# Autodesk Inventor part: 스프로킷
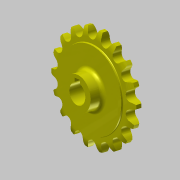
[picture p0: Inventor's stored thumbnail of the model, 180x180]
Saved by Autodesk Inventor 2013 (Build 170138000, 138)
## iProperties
Created: 2016-03
Part Number: 스프로킷
Material: 강철, 탄소
Document SubType Name: 판금
Designer: mduedu
Density: 7.87 g/cm^3
Mass: 301.818 g
Surface Area: 124.882 cm^2
Volume: 38.3505 cm^3
Sheet Metal Rule: 기본값
Author: mduedu
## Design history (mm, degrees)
sketch "스케치1"
  geometry: L1 (0, 5)-(29.5, 5); L2 (29.5, 5)-(29.5, 4.1); L3 (30, 3.6)-(33.625, 3.6); L4 (40, 2)-(40, 0); L5 (40, 0)-(0, 0); L6 (0, 0)-(0, 5); L7 (0, -5)-(29.5, -5); L8 (29.5, -5)-(29.5, -4.1); L9 (30, -3.6)-(33.625, -3.6); L10 (40, -2)-(40, 0); L11 (0, 0)-(0, -5); A1 r 13.5 centre (33.625, -9.9) between (40, 2) and (33.625, 3.6); A2 r 13.5 centre (33.625, 9.9) between (33.625, -3.6) and (40, -2); A3 r 0.5 centre (30, 4.1) between (29.5, 4.1) and (30, 3.6); A4 r 0.5 centre (30, -4.1) between (30, -3.6) and (29.5, -4.1); 2 further points
  constraints: 22 end point, 8 point on circle, 6 symmetric about line, 5 tangent, 4 centre point, 4 parallel, 4 point on line, 1 equal radius, 1 horizontal, 1 perpendicular, 1 other
  dimensions: "d0" = 80 diameter of L4 L6; "d2" = 59 diameter of L2 L6; "d3" = 1.6 vertical distance of L4.start L3.end; "d4" = 3.6 distance from line of L4.end L3; "d5" = 5 distance between parallel lines of L5 L1; "d6" = 13.5 radius of A1; "d15" = 0.5 radius of A3
revolve "회전1" sketch "스케치1" stored, may be unused: angle "d7" = 90 deg
sketch "스케치2" dims "d8" = 65.2, "d11" = 80
  geometry: L1 (0, 0)-(0, 32.6); A1 r 36.57 centre (0, 0) between (-16.231, 32.771) and (0, 36.57); A2 r 3.97 centre (0, 36.57) between (-3.866, 35.665) and (0, 32.6); A3 r 12.7 centre (-16.231, 32.771) between (-3.866, 35.665) and (-5.534, 39.615); A4 r 12.7 centre (16.231, 32.771) between (5.534, 39.615) and (3.866, 35.665); A5 r 3.97 centre (0, 36.57) between (0, 32.6) and (3.866, 35.665); A6 r 40 centre (0, 0) between (5.534, 39.615) and (-5.534, 39.615); 2 further points
  constraints: 12 point on circle, 6 centre point, 4 coincident, 3 symmetric about line, 2 end point, 1 point on line, 1 tangent, 1 vertical, 1 vertical alignment, 7 other
  dimensions: "d10" = 73.14 diameter of A1; "d12" = 12.7 radius of A3
extrude "돌출1" cut sketch "스케치2" stored distance "d13" = 10; taper "d14" = 0 deg
sketch "스케치3"
  geometry: C1 r 12.5 at (0, 0); 1 further point
  constraints: 1 centre point, 1 coincident
  dimensions: "d19" = 25 diameter of C1
extrude "돌출2" join sketch "스케치3" distance "d20" = 10; taper "d21" = 0 deg
fillet "모깎기1" dims "d22" = 3
sketch "스케치4"
  geometry: L1 (-2.5, 0)-(2.5, 0); L2 (2.5, 0)-(2.5, 9.8); L3 (2.5, 9.8)-(-2.5, 9.8); L4 (-2.5, 9.8)-(-2.5, 0); C1 r 7.5 at (0, 0); 2 further points
  constraints: 8 end point, 2 coincident, 2 parallel, 1 centre point, 1 horizontal, 1 midpoint, 1 perpendicular
  dimensions: "d23" = 15 diameter of C1; "d25" = 5 distance of L2.end L3.end; "d26" = 9.8 distance of L1.end L2.end
extrude "돌출3" cut sketch "스케치4" stored distance "d27" = 8; taper "d28" = 0 deg
node "솔리드1"
pattern_circular "원형 패턴1" dims angle "d17" = 360 deg
other parameters: "K계수" = 4.4, "BendRadius" = 0.5 (derived), "BendReliefWidth" = 0.5 (derived), "BendReliefDepth" = 0.25 (derived), "CornerReliefSize" = 2 (derived), "SeamGap" = 0.01, "MinimumRemnant" = 1 (derived), "TransitionRadius" = 0.5 (= BendRadius)
